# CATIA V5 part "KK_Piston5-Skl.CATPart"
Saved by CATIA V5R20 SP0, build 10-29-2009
Part number: Piston5-Skl
Bounding box of the stored display mesh (mm): x -49.705 to -43.186, y -86.772 to -48.269, z 0 to 100
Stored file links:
  G:\Khaled_CFAO_2011\ST2M\ST2M_GR1\msallin\Khaled\Version_Finale\KK_Piston5-Skl.CATPart
  C:\Users\Mathieu\Desktop\Think Motion\JOUG-MELEE2.CATProduct
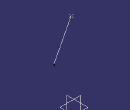
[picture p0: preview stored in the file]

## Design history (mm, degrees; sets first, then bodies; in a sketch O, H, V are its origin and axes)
External parameters (linked from other documents)
  `External.Taille du joug` = 100 mm
Set1
  Point1: linked copy from another document
  Point2: linked copy from another document
Set2
  Line1: type PtPt, FirstPoint Point1, SecondPoint Point2
  Point3: (0, 0, 0), relative to Point1
Body1 (main body)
